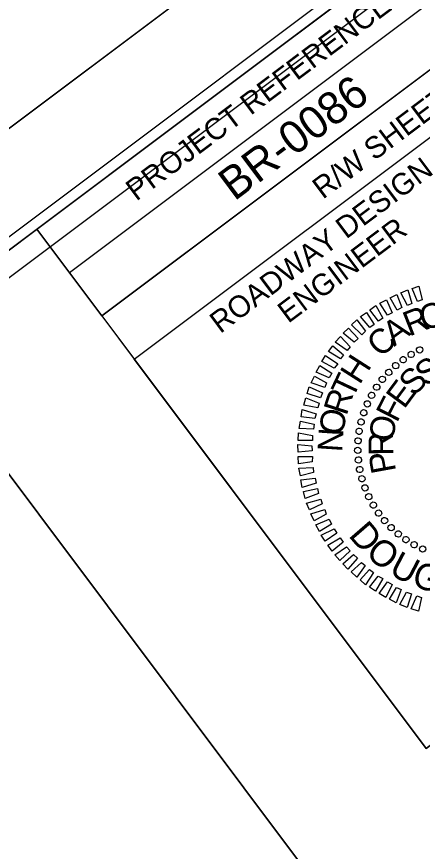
# Model space of a CAD drawing. Extents: x 2186558 to 2188589, y 629855 to 631741.
# Drawn here: x 2187767.1 to 2187861, y 631449 to 631641.9 of the extents above; entities that cross this region are included whole.
import ezdxf

# ---------------------------------------------------------------- set-up
doc = ezdxf.new("R2010")
doc.units = 0
for name, color, linetype in [('Scratch_Level_8', 7, 'Continuous'), ('Sheet Cutting Line CELL', 7, 'Continuous'), ('Sheet Data Field CELL', 7, 'Continuous'), ('Sheet PE Seal Cell', 7, 'Continuous'), ('Sheet Plan CELL', 7, 'Continuous'), ('Sheet Plan Layout CELL', 7, 'Continuous'), ('Sheet Plot Border Inside CELL', 7, 'Continuous'), ('Sheet Plot Border Outside CELL', 7, 'Continuous')]:
    doc.layers.add(name, color=color, linetype=linetype)

msp = doc.modelspace()

# ---------------------------------------------------------------- linework, layer by layer
at = {"layer": 'Scratch_Level_8'}
msp.add_lwpolyline([(2186738.7, 630811.99), (2187930.9, 631705.79), (2188554.73, 630873.69), (2187362.53, 629979.89)], close=True, dxfattribs=at)
at = {"layer": 'Sheet Cutting Line CELL'}
msp.add_line((2187932, 631741), (2186585.01, 630731.15), dxfattribs=at)
at = {"layer": 'Sheet PE Seal Cell'}
for p, q in [((2187860.37, 631564.89), (2187860.37, 631564.89)), ((2187856.55, 631562.65), (2187856.55, 631562.65)), ((2187858.42, 631563.87), (2187858.42, 631563.87)), ((2187854.8, 631561.27), (2187854.8, 631561.27)), ((2187853.24, 631559.72), (2187853.24, 631559.72)), ((2187851.7, 631558.06), (2187851.7, 631558.06)), ((2187850.36, 631556.3), (2187850.36, 631556.3)), ((2187849.23, 631554.44), (2187849.23, 631554.44)), ((2187848.26, 631552.44), (2187848.26, 631552.44)), ((2187847.42, 631550.36), (2187847.42, 631550.36)), ((2187846.76, 631548.28), (2187846.76, 631548.28)), ((2187846.34, 631546.06), (2187846.34, 631546.06)), ((2187846.06, 631543.9), (2187846.06, 631543.9)), ((2187846.03, 631541.66), (2187846.03, 631541.66)), ((2187846.11, 631539.44), (2187846.11, 631539.44)), ((2187846.49, 631537.25), (2187846.49, 631537.25)), ((2187846.98, 631535.09), (2187846.98, 631535.09)), ((2187847.69, 631532.96), (2187847.69, 631532.96)), ((2187848.6, 631530.99), (2187848.6, 631530.99)), ((2187849.62, 631529.03), (2187849.62, 631529.03)), ((2187850.84, 631527.16), (2187850.84, 631527.16)), ((2187852.21, 631525.41), (2187852.21, 631525.41)), ((2187853.76, 631523.85), (2187853.76, 631523.85)), ((2187855.42, 631522.31), (2187855.42, 631522.31)), ((2187857.19, 631520.98), (2187857.19, 631520.98)), ((2187859.05, 631519.84), (2187859.05, 631519.84))]:
    msp.add_line(p, q, dxfattribs=at)
for points in [[(2187859.88, 631576.1), (2187858.6, 631579.06), (2187860.16, 631579.6), (2187860.94, 631576.45)], [(2187855.14, 631574.06), (2187853.56, 631576.93), (2187855.05, 631577.73), (2187856.2, 631574.67)], [(2187857.54, 631575.16), (2187855.97, 631578.1), (2187857.59, 631578.81), (2187858.54, 631575.6)], [(2187852.95, 631572.93), (2187851.14, 631575.68), (2187852.66, 631576.44), (2187854.04, 631573.49)], [(2187850.84, 631571.53), (2187848.86, 631574.16), (2187850.23, 631575.12), (2187851.84, 631572.22)], [(2187846.99, 631568.39), (2187844.6, 631570.65), (2187845.85, 631571.84), (2187847.87, 631569.24)], [(2187848.86, 631570.11), (2187846.68, 631572.59), (2187848.05, 631573.55), (2187849.86, 631570.8)], [(2187845.23, 631566.69), (2187842.63, 631568.79), (2187843.88, 631569.92), (2187846.11, 631567.54)], [(2187843.62, 631564.78), (2187840.85, 631566.7), (2187842.02, 631568.01), (2187844.32, 631565.62)], [(2187842.07, 631562.8), (2187839.31, 631564.53), (2187840.3, 631565.84), (2187842.71, 631563.72)], [(2187840.57, 631560.66), (2187837.76, 631562.22), (2187838.61, 631563.62), (2187841.4, 631561.66)], [(2187839.43, 631558.47), (2187836.43, 631559.77), (2187837.26, 631561.28), (2187840.04, 631559.51)], [(2187838.42, 631556.2), (2187835.28, 631557.26), (2187836.05, 631558.85), (2187838.82, 631557.26)], [(2187837.39, 631553.85), (2187834.35, 631554.79), (2187834.82, 631556.35), (2187837.92, 631555)], [(2187836.77, 631551.48), (2187833.57, 631552.11), (2187834.02, 631553.79), (2187837.14, 631552.58)], [(2187836.09, 631549.01), (2187832.97, 631549.45), (2187833.21, 631551.15), (2187836.43, 631550.15)], [(2187835.82, 631546.59), (2187832.5, 631546.7), (2187832.82, 631548.39), (2187835.98, 631547.72)], [(2187835.55, 631543.98), (2187832.26, 631543.98), (2187832.36, 631545.71), (2187835.57, 631545.14)], [(2187835.49, 631541.53), (2187832.27, 631541.27), (2187832.16, 631543.02), (2187835.44, 631542.7)], [(2187835.49, 631539), (2187832.31, 631538.52), (2187832.27, 631540.26), (2187835.59, 631540.22)], [(2187835.83, 631536.53), (2187832.76, 631535.81), (2187832.43, 631537.52), (2187835.74, 631537.67)], [(2187836.42, 631534.06), (2187833.21, 631533.11), (2187832.87, 631534.82), (2187836.15, 631535.26)], [(2187836.94, 631531.67), (2187833.89, 631530.52), (2187833.47, 631532.17), (2187836.75, 631532.86)], [(2187837.79, 631529.27), (2187834.89, 631527.92), (2187834.17, 631529.47), (2187837.48, 631530.37)], [(2187838.73, 631526.94), (2187835.97, 631525.38), (2187835.22, 631526.96), (2187838.41, 631528.03)], [(2187839.95, 631524.63), (2187837.18, 631522.93), (2187836.31, 631524.42), (2187839.42, 631525.75)], [(2187841.21, 631522.53), (2187838.51, 631520.64), (2187837.59, 631522.03), (2187840.56, 631523.56)], [(2187842.69, 631520.48), (2187840.15, 631518.38), (2187839.11, 631519.76), (2187841.96, 631521.45)], [(2187844.25, 631518.48), (2187841.86, 631516.18), (2187840.74, 631517.5), (2187843.44, 631519.39)], [(2187845.95, 631516.72), (2187843.74, 631514.18), (2187842.59, 631515.46), (2187845.06, 631517.57)], [(2187847.77, 631515.05), (2187845.8, 631512.37), (2187844.52, 631513.56), (2187846.89, 631515.72)], [(2187849.71, 631513.47), (2187847.82, 631510.6), (2187846.58, 631511.75), (2187848.79, 631514.11)], [(2187851.82, 631512.01), (2187850.14, 631509.11), (2187848.75, 631510.03), (2187850.78, 631512.56)], [(2187853.98, 631510.66), (2187852.5, 631507.65), (2187851, 631508.55), (2187852.9, 631511.24)], [(2187856.09, 631509.52), (2187854.89, 631506.41), (2187853.42, 631507.27), (2187855.03, 631509.93)], [(2187858.48, 631508.53), (2187857.49, 631505.38), (2187855.81, 631506.02), (2187857.31, 631508.92)], [(2187860.78, 631507.66), (2187860.07, 631504.47), (2187858.42, 631505.07), (2187859.72, 631508.07)]]:
    msp.add_lwpolyline(points, close=True, dxfattribs=at)
for centre, major_axis in [((2187858.4, 631563.84), (-0.374, 0.626)), ((2187860.35, 631564.9), (-0.318, 0.656)), ((2187856.55, 631562.62), (-0.427, 0.591)), ((2187853.21, 631559.73), (-0.523, 0.507)), ((2187854.82, 631561.25), (-0.477, 0.551)), ((2187851.73, 631558.07), (-0.566, 0.46)), ((2187850.41, 631556.29), (-0.604, 0.409)), ((2187849.25, 631554.41), (-0.637, 0.355)), ((2187848.26, 631552.42), (-0.665, 0.298)), ((2187847.44, 631550.37), (-0.689, 0.239)), ((2187846.81, 631548.24), (-0.707, 0.178)), ((2187846.36, 631546.07), (-0.72, 0.116)), ((2187846.11, 631543.87), (-0.727, 0.052)), ((2187846.05, 631541.66), (-0.729, -0.011)), ((2187846.18, 631539.45), (-0.725, -0.075)), ((2187846.5, 631537.25), (-0.716, -0.138)), ((2187847.01, 631535.1), (-0.701, -0.2)), ((2187847.71, 631533), (-0.681, -0.26)), ((2187848.59, 631530.96), (-0.656, -0.318)), ((2187849.64, 631529.01), (-0.626, -0.374)), ((2187850.86, 631527.17), (-0.591, -0.427)), ((2187852.24, 631525.43), (-0.551, -0.477)), ((2187853.76, 631523.82), (-0.507, -0.523)), ((2187855.42, 631522.35), (-0.46, -0.566)), ((2187857.19, 631521.03), (-0.409, -0.604)), ((2187859.08, 631519.86), (-0.355, -0.637)), ((2187861.06, 631518.87), (-0.298, -0.665))]:
    msp.add_ellipse(centre, major_axis=major_axis, ratio=0.999708, dxfattribs=at)
at = {"layer": 'Sheet Plan CELL'}
for p, q in [((2187779.33, 631582.77), (2187939.4, 631702.76)), ((2187786.86, 631572.75), (2187946.9, 631692.76)), ((2187786.86, 631572.75), (2187946.9, 631692.76)), ((2187786.86, 631572.75), (2187794.35, 631562.75))]:
    msp.add_line(p, q, dxfattribs=at)
for points in [[(2187931.9, 631712.82), (2186731.71, 630813.02), (2187361.55, 629972.91), (2188561.73, 630872.69)], [(2187771.81, 631592.82), (2187931.9, 631712.82), (2187946.9, 631692.76), (2187786.86, 631572.75)], [(2187794.35, 631562.75), (2187874.4, 631622.77), (2187941.9, 631532.75), (2187861.84, 631472.76)], [(2187361.55, 629972.91), (2186731.7, 630812.99), (2187771.81, 631592.82), (2187861.84, 631472.76), (2188021.9, 631592.74), (2188561.73, 630872.69)]]:
    msp.add_lwpolyline(points, close=True, dxfattribs=at)
at = {"layer": 'Sheet Plan Layout CELL'}
for points in [[(2187867.31, 631400.07), (2188058.75, 631543.6), (2187931.91, 631712.83), (2187740.45, 631569.29)], [(2186731.7, 630812.99), (2187361.55, 629972.91), (2188561.72, 630872.68), (2188058.73, 631543.59), (2187867.31, 631400.07), (2187740.45, 631569.29)]]:
    msp.add_lwpolyline(points, close=True, dxfattribs=at)
at = {"layer": 'Sheet Plot Border Inside CELL'}
msp.add_lwpolyline([(2187240.25, 629878.83), (2188573.22, 630878.18), (2187940.39, 631722.3), (2186607.41, 630722.95)], close=True, dxfattribs=at)
at = {"layer": 'Sheet Plot Border Outside CELL'}
msp.add_lwpolyline([(2187241.85, 629855.03), (2188588.83, 630864.88), (2187932, 631741), (2186585.01, 630731.15)], close=True, dxfattribs=at)

# ---------------------------------------------------------------- texts
at = {"layer": 'Sheet Data Field CELL'}
msp.add_text('BR-0086', height=7.5, rotation=36.8593, dxfattribs=at).set_placement((2187817.49, 631599.16))
at = {"layer": 'Sheet PE Seal Cell'}
for s, height, rotation, p in [('O', 5.71, 14.3041, (2187861.12, 631569.37)), ('R', 5.71, 21.504, (2187857.95, 631567.95)), ('A', 5.71, 35.9032, (2187854.43, 631565.56)), ('C', 5.71, 43.1028, (2187851.41, 631562.91)), ('H', 5.71, 57.5024, (2187846.47, 631556.67)), ('S', 5.71, 34.7833, (2187861.81, 631556.22)), ('S', 5.71, 44.1385, (2187858.93, 631553.99)), ('T', 5.71, 64.7027, (2187844.85, 631553.36)), ('E', 5.71, 53.494, (2187856.77, 631551.05)), ('R', 5.71, 71.9034, (2187843.43, 631549.51)), ('F', 5.71, 62.85, (2187855.09, 631547.89)), ('O', 5.71, 79.1047, (2187842.52, 631544.91)), ('O', 5.71, 81.5642, (2187854.21, 631543.49)), ('N', 5.71, 86.3064, (2187842.42, 631541.16)), ('R', 5.71, 90.9226, (2187854.29, 631540.45)), ('P', 5.71, 100.2818, (2187854.93, 631536.88)), ('D', 6.07, 310.8986, (2187843.72, 631521.93)), ('O', 6.07, 320.7744, (2187847.58, 631517.48)), ('U', 6.07, 332.3348, (2187852.99, 631513.19)), ('G', 6.07, 342.2724, (2187858.25, 631510.44))]:
    msp.add_text(s, height=height, rotation=rotation, dxfattribs=at).set_placement(p)
at = {"layer": 'Sheet Plan CELL'}
for s, height, p in [('PROJECT REFERENCE NO.', 5.0001, (2187794.81, 631599.15)), ('R/W SHEET NO.', 5.0001, (2187837.98, 631599.59)), ('ROADWAY DESIGN', 5.0001, (2187814.23, 631568.54)), ('ENGINEER', 5, (2187829.95, 631570.9))]:
    msp.add_text(s, height=height, rotation=36.8593, dxfattribs=at).set_placement(p)

doc.saveas('drawing.dxf')
